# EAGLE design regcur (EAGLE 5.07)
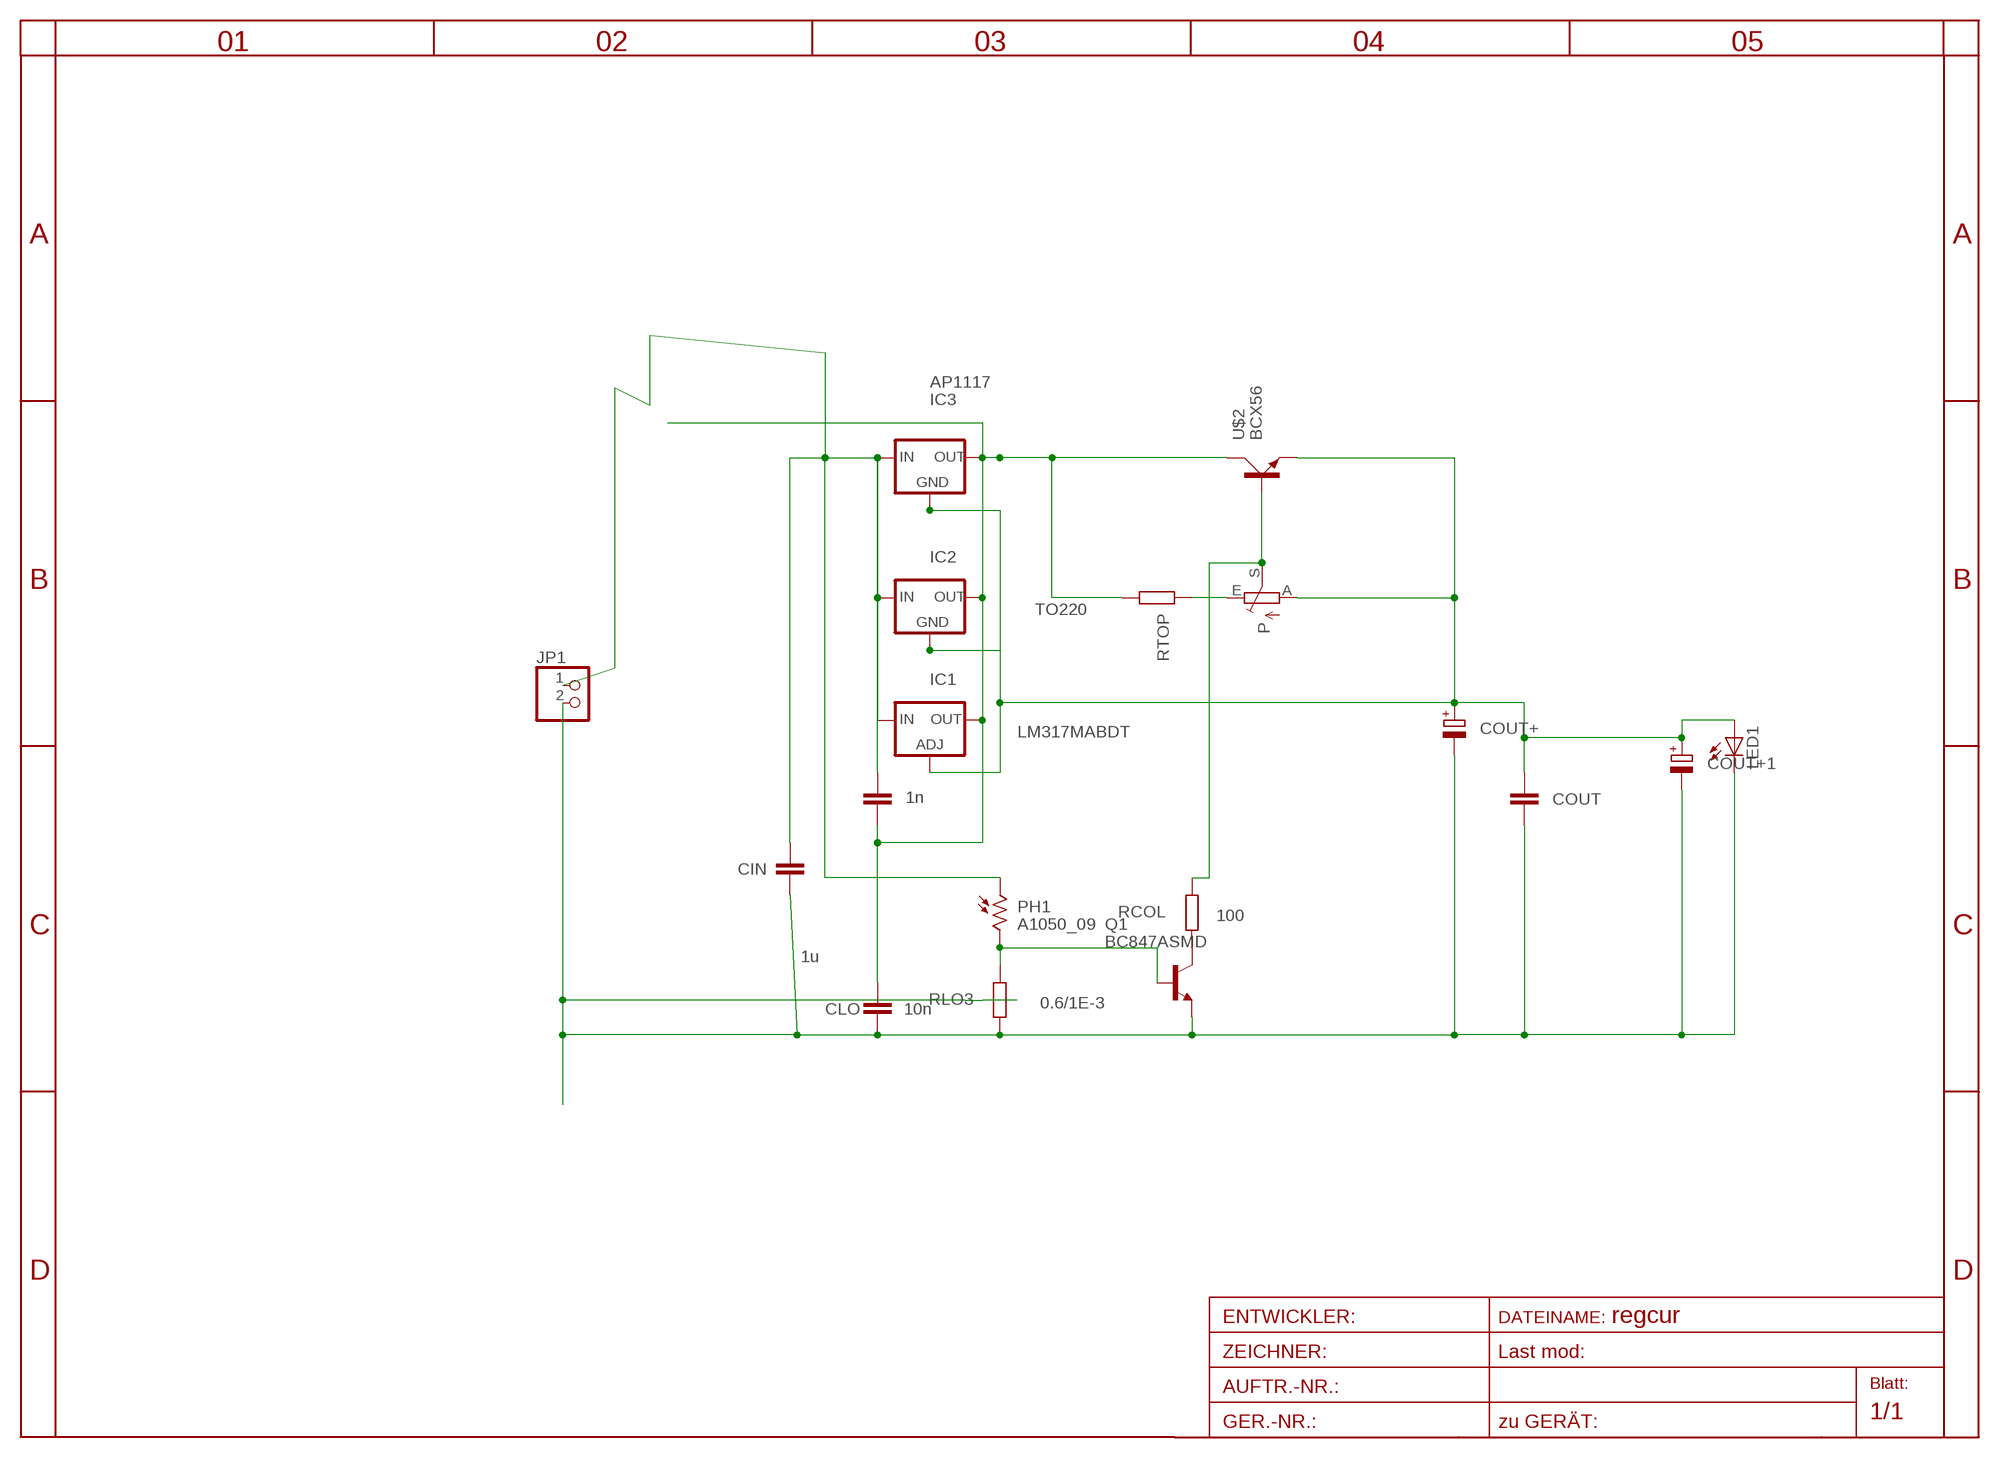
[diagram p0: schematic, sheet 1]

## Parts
CHI  1n  C-EUC0805  [C0805]
CIN  1u  C-EUC1206  [C1206]
CLO  10n  C-EUC0805  [C0805]
COUT  C-EUC1206  [C1206]
COUT+  CPOL-EUE3.5-10  [E3,5-10]
COUT+1  CPOL-EUE7.5-16  [E7,5-16]
IC1  LM317MABDT  [DPACK]
IC2  TO220  78XXS  [78XXS]
IC3  AP1117  [SOT223]
JP1  PINHD-1X2STR  [1X02]
LED1  LED1W1MM6  [1W1MM6]
P  TRIM_EU-RAND160  [RANDL]
PH1  A1050_09  [T0-46-A10XX]
Q1  BC847ASMD  [SOT23]
RCOL  100  R-EU_R0805  [R0805]
RLO3  0.6/1E-3  R-EU_R0805  [R0805]
RTOP  R-EU_R0805  [R0805]
U$2  BCX56  [SOT223]

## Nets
GND: CIN.2 CLO.2 COUT+1.- COUT+.- COUT.2 JP1.2 LED1.C Q1.2(E) RLO3.1
IN: CHI.1 CIN.1 IC1.3(IN) IC2.IN IC3.3(IN) JP1.1 PH1.1
N$3: Q1.3(C) RCOL.1
N$4: P.E RTOP.1
N$5: P.S RCOL.2 U$2.1(B)
N$6: PH1.2 Q1.1(B) RLO3.2
OUT: COUT+1.+ COUT+.+ COUT.1 IC1.1(ADJ) IC2.GND IC3.1(GND) LED1.A P.A U$2.3(E)
OUT1: CHI.2 CLO.1 IC1.4(OUT) IC2.OUT IC3.2(OUT) IC3.4(TAB) RTOP.2 U$2.2(C)

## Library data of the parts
CHI CIN CLO COUT = rcl:C-EU: CAPACITOR, European symbol
COUT+ COUT+1 = rcl:CPOL-EU: POLARIZED CAPACITOR, European symbol
IC1 = v-reg:LM317?*: 500 mA Adjustable Output Positive Voltage Regulator Source: http://www.onsemi.co.jp .. LM317M-D.PDF
IC2 = v-reg:78XXS: VOLTAGE REGULATOR
IC3 = v-reg:AP1117
JP1 = pinhead:PINHD-1X2: PIN HEADER
LED1 = led:LED: LED
P = pot:TRIM_EU-: POTENTIOMETER
PH1 = photo-elements:A10: Sensor Robust Light Sensing Applications
Q1 = transistor-npn:BC847*: NPN Transistor
RCOL RLO3 RTOP = rcl:R-EU_: RESISTOR, European symbol
U$2 = transistor-power:BCX56

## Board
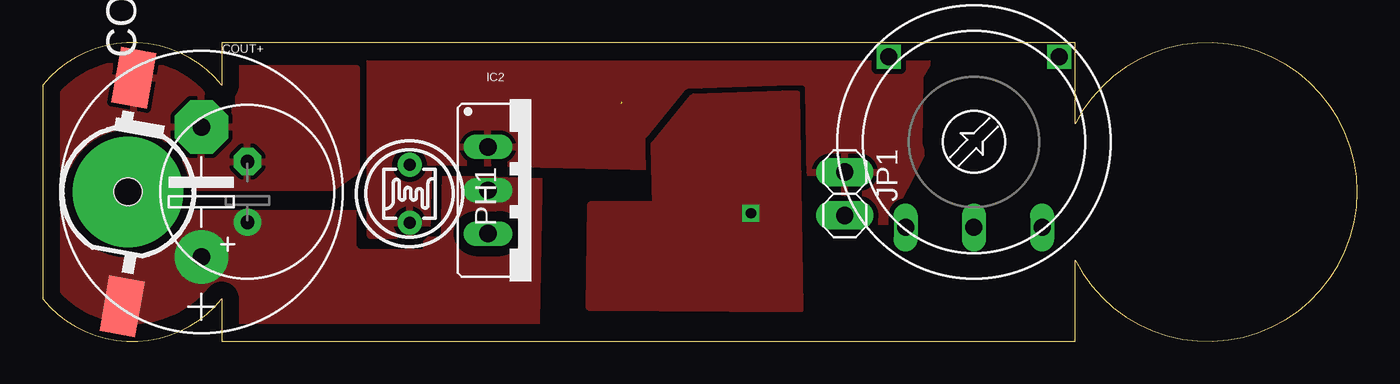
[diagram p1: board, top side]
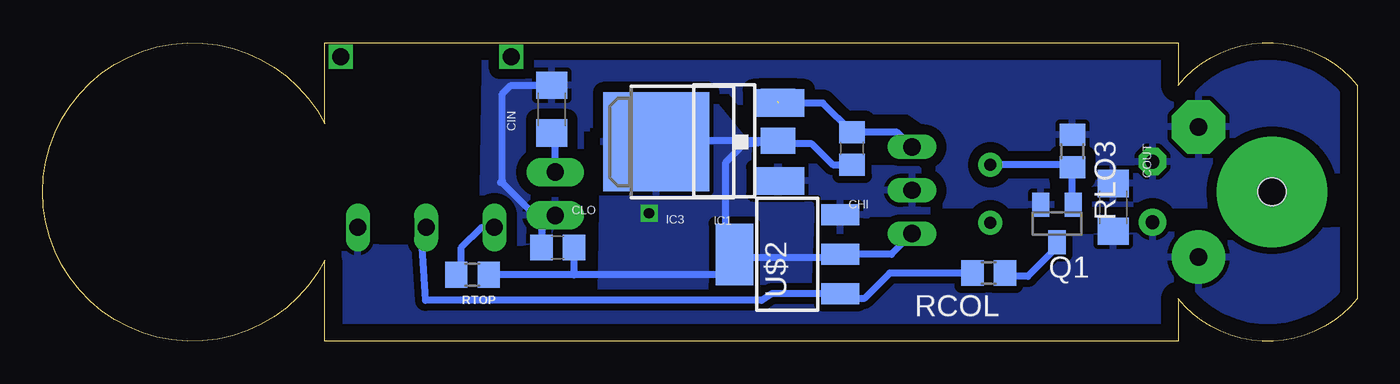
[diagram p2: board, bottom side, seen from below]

Size 77.03 x 17.5 mm. Coordinates in mm from the lower left corner, seen from the top.
Outline: 10.5,0 60.5,0 60.5,4.75 arc306 60.5,12.75 60.5,17.5
Outline: 60.5,17.5 10.5,17.5
Outline: 10.5,17.5 10.5,15
Outline: 10.5,15 arc102 0,15
Outline: 0,15 0,2.5
Outline: 0,2.5 arc102 10.5,2.5
Outline: 10.5,2.5 10.5,0
Outline: 60.5,17.5 10.5,17.5
Outline: 10.5,17.5 10.5,15
Outline: 10.5,15 arc102 0,15
Outline: 0,15 0,2.5
Outline: 0,2.5 arc102 10.5,2.5
Outline: 10.5,2.5 10.5,0
Copper layers (1*16): Top 0.035mm / dielectric 1.5mm / Bottom 0.035mm
Design rules "default *": minimum track width 10mil, minimum drill 20mil, track to track 8mil, track to pad 8mil, pad to pad 8mil, via to via 8mil, smd to smd 8mil, copper to edge 40mil, drill to drill 8mil, minimum pad ring 8mil, minimum via ring 8mil, stop-mask expansion 8mil, vias tented up to drill 0mil, thermal gap 10mil

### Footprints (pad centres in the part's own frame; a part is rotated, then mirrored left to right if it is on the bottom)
C0805 = smd 1.3 x 1.5: 1 -0.95,0; 2 0.95,0
C1206 = smd 1.6 x 1.8: 1 -1.4,0; 2 1.4,0
E3,5-10 = drill 0.813 pad 1.6 round: + -1.778,0 | drill 0.813 pad 1.6 octagon: - 1.778,0
E7,5-16 = drill 1.016 pad 3.15 round: + -3.81,0 | drill 1.016 pad 3.15 octagon: - 3.81,0
DPACK = smd 1.6 x 3: 1 -2.28,-4.8; 3 2.28,-4.8 | smd 5.8 x 6.2: 4 0,2.38
78XXS = drill 1.016 long: GND 0,-2.54; IN -2.54,-2.54; OUT 2.54,-2.54
SOT223 = smd 1.5 x 2: 1 -2.3,-3.15; 2 0,-3.15; 3 2.3,-3.15 | smd 3.8 x 2: 4 0,3.15
1X02 = drill 1.016 pad 1.676 long: 1 -1.27,0; 2 1.27,0
1W1MM6 = smd 3.3 x 2.1: A -6.65,-0.82; C 6.65,0.82 | drill 1.6 pad 6.452 round: P$1 0,0 | hole 1.6: 0,0
RANDL = drill 1 long: A -4,5; E 4,5; S 0,5 | drill 1 square: P$1 -5,-5; P$2 5,-5
T0-46-A10XX = drill 0.7 pad 1.4 round: 1 -1.7,0; 2 1.7,0
SOT23 = smd 1 x 1.4: 1 -0.95,-1.1; 2 0.95,-1.1; 3 0,1.1
R0805 = smd 1.3 x 1.5: 1 -0.95,0; 2 0.95,0
SOT223' = smd 1.219 x 2.235: 1 -2.311,-3.099; 2 0,-3.099; 3 2.311,-3.099 | smd 3.6 x 2.2: 4 0,3.099

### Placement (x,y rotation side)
CHI  29.6,11.3 270 bottom
CIN  47.2,13.6 90 bottom
CLO  46.85,5.5 180 bottom
COUT  14.3,7.85 90 bottom
COUT+  12,8.75 90 top
COUT+1  9.3,8.75 90 top
IC1  38.7,11.68 90 bottom
IC2  28.63,8.85 270 top
IC3  37.1,11.75 90 bottom
JP1  47,8.65 270 top
LED1  5,8.75 80 top
P  54.57,11.68 180 top
PH1  21.5,8.65 90 top
Q1  17.6,6.9 180 bottom
RCOL  21.6,4 180 bottom
RLO3  16.7,11.15 270 bottom
RTOP  51.85,3.9 0 bottom
U$2  BCX56  [SOT223']  33.4,5.1 90 bottom

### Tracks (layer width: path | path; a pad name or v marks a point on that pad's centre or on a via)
GND
  Bottom 0.406: CLO.2 47.8,6.58 JP1.2 47.02,7.4 48.2,7.4 50.1,9.3 50.2,9.3 50.1,9.4 50.1,14.5 49.6,15 CIN.2
  pour Bottom (isolate 0.61, rank 2): 0,15.5 arc-92 11,15 11,17.5 51.1,17.6 51.3,5.4 45.5,6.4 45.5,12.5 34.9,12.2 32,13.55 31,13.5 26.3,13.5 24.4,12.2 24.4,11.2 24.5,10.5 24.9,8 0.4,8
  pour Top (isolate 0.406, rank 3): 0.5,15 arc-78 10,15 10,13.5 11.5,13.5 11.5,16 18.4,16 18.4,10 17,9 9,9 6,12 3.5,12 0.5,9.5
IN  (1 unrouted)
  Bottom 0.406: IC1.3 31.31,13.96 CHI.1 26.95,12.25 IC2.IN | JP1.1 47,12 CIN.1
  pour Top (isolate 0.305, rank 2): 52,16.57 51.4,15.5 51.34,11.5 51.5,11 49.5,7 45,7 45,10 22.6,10.5 22.5,6.2 19.2,6.2 19.2,16.5
N$3
  Bottom 0.406: Q1.3 17.6,5.5 19.3,3.8 20.45,3.8 RCOL.1
N$4
  Bottom 0.406: P.E 51.32,6.68 52.5,5.5 52.5,4.2 RTOP.1
N$5
  Bottom 0.406: RCOL.2 27.4,4 28.9,2.5 30.01,2.5 U$2.1 34.31,2.79 34.9,2.4 54.6,2.4 54.8,5.5 54.8,6.45 P.S
N$6
  Bottom 0.406: PH1.2 16.85,10.35 RLO3.2 16.7,8.05 Q1.1
OUT
  pour Bottom (isolate 0.406, rank 3): 44.3,5.3 59.5,5.5 59.5,0.5 0.5,0.5 0.5,6.5
  pour Top (isolate 0.61, rank 4, no thermals): 28.9,-0.4 10.5,0 10.5,1.5 arc-67 0,1.5 0,7.5 23.1,7.5 23.1,10.3 29.1,10.3
  pour Bottom (isolate 0.406, rank 3): 25,9.3 25.8,10.1 28.6,10.1 28.7,10.2 35,10.2 35.6,9.6 35.6,8.2 35.3,7.9 32,7.9 31.8,7.7 31.8,6.5 29.6,6.5 28.6,7.5 25.2,7.5
OUT1  (via drill 0.6)
  Bottom 0.406: IC2.OUT 27.3,5.1 U$2.2 30.5,4.9 36.3,4.9 36.5,5.1 | IC3.2 IC3.4 | IC3.2 35.95,11.55 37,10.5 37,5.6 36.5,5.1 | CHI.2 30.75,10.35 32,11.6 33.9,11.6 IC3.2 | 45.9,3.9 36.1,3.9 36.5,5.1 | 45.9,3.9 RTOP.2 | 45.9,3.9 CLO.1
  other vias: 41.5,7.5
  pour Top: 32.1,8 32,2 44.4,1.9 44.2,14.5 38.1,14.3 35.8,11.5 35.9,8
  pour Bottom (isolate 0.406): 32,8 32.2,2.9 44.3,2.8 44.1,14.5 38,14.3 35.7,11.5 35.8,8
